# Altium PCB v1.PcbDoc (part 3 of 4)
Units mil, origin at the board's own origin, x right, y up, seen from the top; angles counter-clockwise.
Board outline 4875 x 2022 mil, 4 copper layers (Top Layer, Signal Layer 1, Signal Layer 2, Bottom Layer), stack 64.834 mil thick; 432 components, 288 nets, 1177 pads, 637 vias.
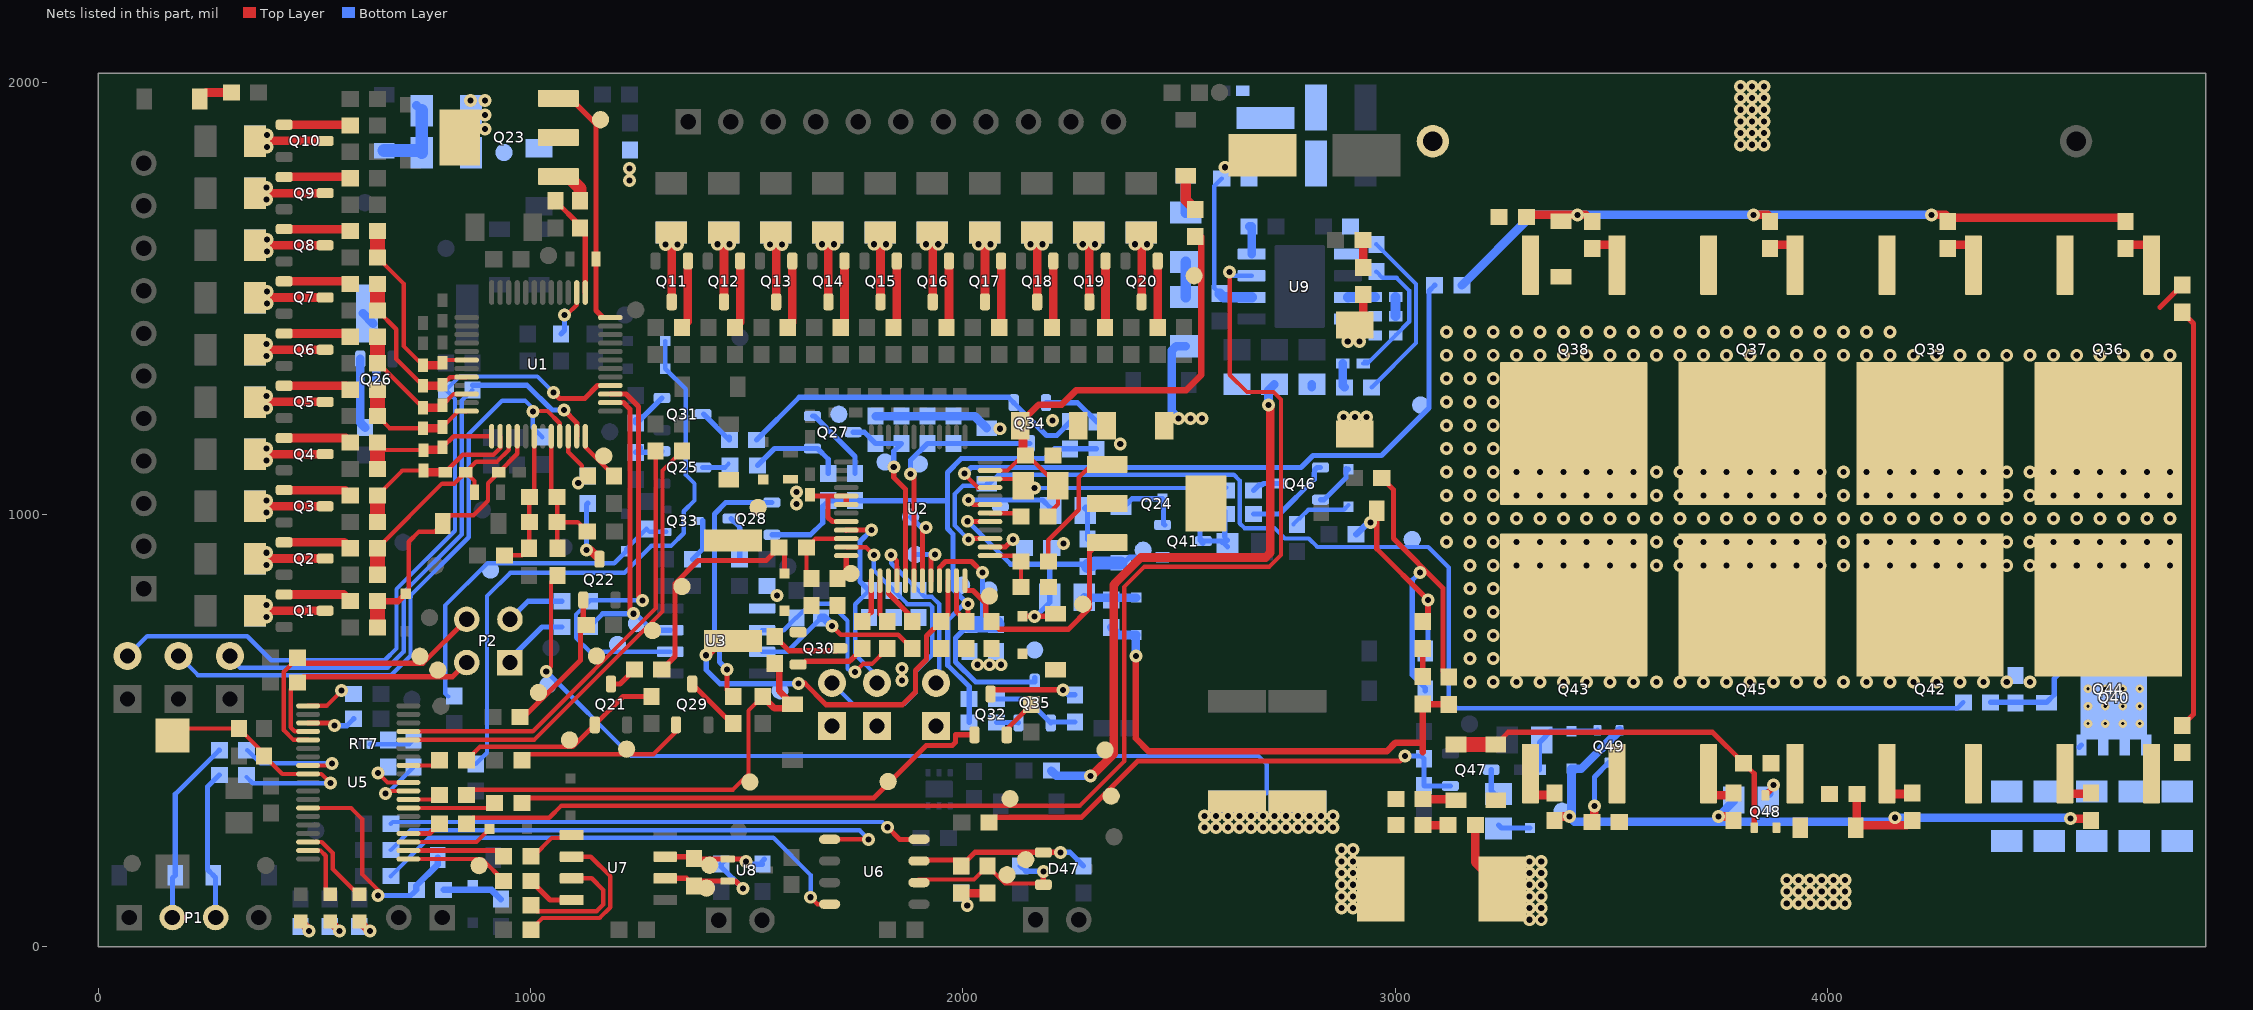
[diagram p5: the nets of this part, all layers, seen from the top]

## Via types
v1: diameter 30, hole 14, Top Layer to Bottom Layer, 615 vias
v2: diameter 19.68, hole 7.87, Top Layer to Bottom Layer, 18 vias
v3: diameter 19.68, hole 7.87, Top Layer to Bottom Layer, tented both sides, 4 vias

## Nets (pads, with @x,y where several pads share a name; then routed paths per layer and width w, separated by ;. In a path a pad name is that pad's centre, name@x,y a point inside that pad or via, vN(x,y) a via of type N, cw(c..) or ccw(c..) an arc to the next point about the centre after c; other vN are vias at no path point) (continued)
LED2: D43.2 U5.18 | length 138.8
  Top Layer w10: U5.18@484.86,223.17 513.83,223.17 526,211 526,132.5 D43.2@536,122.5
LED3: D44.2 U5.17 | length 190.9
  Top Layer w10: U5.17@484.86,242.85 516.77,242.85 542,217.63 542,180.23 599.73,122.5 D44.2@604,122.5
NetC27_1: C27.1 R92.2 U1.22 | length 137.7
  Top Layer w10: U1.22@1086.9,1181.66 1086.9,1145.1 1118.5,1113.5 1118.5,1102.87 C27.1@1132,1089.37 C27.1@1122.63,1080
  Bottom Layer w10: R92.2@1122.5,1080 R92.2@1132,1089.5
  other v1: 1110,1073
NetC28_1: C28.1 R93.2 U2.22 | length 176.9
  Top Layer w10: C28.1@1649.54,852.5 1638.01,864.03 R93.2@1638.01,924 1658.75,944.73 U2.22@1730.04,944.73
NetC30_1: C30.1 pad.1@1169,1136 U1.24 | length 119.9
  Top Layer w10: U1.24@1126.27,1181.66 1126.27,1156.83 1193,1090.1 C30.1@1193,1089.37
NetC31_1: C31.1 pad.1@1741,864.03 U2.24 | length 61.2
  Top Layer w12: C31.1@1709.92,852.5 1730.04,872.61 U2.24@1730.04,905.36
NetC40_1: C40.1 pad.1@1161.55,1914 Q23.3 U1.36 | length 583.9
  Top Layer w12: Q23.3@1064.17,1965.55 1089.45,1965.55 1151,1904 C40.1@1151,1592 1151,1472.53 1167.26,1456.27 U1.36@1184.34,1456.27
NetC41_1: C41.1 pad.1@2061,812 pad.1@2277.23,793 Q24.3 U2.36 | length 543.6
  Top Layer w12: U2.36@2004.65,847.29 2004.65,828.35 2008,825 2023,825 2053,795 2053,765.94 C41.1@2065.8,753.15 2083.94,735 2244,735 2293,784 2293,914 Q24.3@2314.45,935.45
NetC44_1: C44.1 pad.1@938,1838 Q23.2 Q23.4 R107.1 R111.1
  other v1: 894,1892 894,1925 861,1958 894,1958
NetC45_1: C45.1 Q24.2 Q24.4 R108.1 | length 199.6
  Bottom Layer w20: v1(2499,1223) 2483.33,1238.67 2483.33,1380 2493.24,1389.91 R108.1@2515.33,1389.91
  other v1: 2526,1223 2553,1223
NetC50_2: C50.2 D16.2 pad.1@907,872 Q33.1 R127.2 | length 804.4
  Bottom Layer w10: R127.2@809,579.5 802,586.5 802,790 900,888 1193.49,888 D16.2@1221.19,915.69 1221.19,920.69 C50.2@1268,967.5 1275.09,960.41 Q33.1@1313.6,960.41
NetC57_1: C57.1 C58.2 | length 977.5
  Top Layer w12: C58.2@4821,512.5 4847,538.5 4847,1442.5 C57.1@4821,1468.5
NetC57_2: C57.2 D17.2 F1.1 Q36.3 Q37.3 Q38.3 Q39.3 R140.2 | length 72.8
  Top Layer w12: 4769.5,1480 C57.2@4821,1531.5
  other v1: 3799,1856 3826,1856 3853,1856 3799,1883 3826,1883 3853,1883 3799,1910 3826,1910 3853,1910 3799,1937 3826,1937 3853,1937 3799,1964 3826,1964 3853,1964 3799,1991 3826,1991 3853,1991
NetC59_1: C59.1 pad.1@2343,349 Q47.1 R162.2 R165.2 | length 1196.3
  Top Layer w12: R162.2@2060.28,288 2072.28,300 2274.03,300 2404.47,430.44 3011.44,430.44 v1(3023,442)
  Bottom Layer w12: v1(3023,442) 3060.5,442 C59.1@3067,435.5 R165.2@3067,373.5 3067.9,372.6 Q47.1@3127.76,372.6
NetC60_1: C60.1 C61.2 | length 58
  Top Layer w20: C60.1@3064.5,282 C61.2@3122.5,282
NetC70_2: C70.2 R205.1 R206.2 | length 61
  Top Layer w20: R206.2@1996,124.5 R205.1@2057,124.5
  other v1: 2010,96
NetC71_1: C71.1 D48.1 L5.1
NetC72_1: C72.1 L5.2 R209.1
NetC73_1: C73.1 C74.1 R209.2 U9.2 | length 356.4
  Bottom Layer w10: C73.1@2594.33,1511.5 2581.33,1524.5 2581.33,1760.5 R209.2@2598.84,1778
  Bottom Layer w25: C73.1@2594.33,1511.5 2602.83,1503 U9.2@2668.11,1503
  other v1: 2606.33,1804
NetC75_1: C75.1 R212.1 | length 64
  Top Layer w20: C75.1@2925.11,1636 2926.33,1634.78 R212.1@2926.33,1572.5
NetC76_1: C76.1 R211.2 | length 44.5
  Bottom Layer w23: C76.1@3000.95,1459.5 R211.2@3000.95,1504
NetC76_2: C76.2 L6.1 pad.1@2917.33,1421 R212.2 R213.1 U9.8 | length 50.8
  Top Layer w20: L6.1@2926.33,1462.98 R212.2@2926.33,1509.5
  Bottom Layer w10: U9.8@2890.55,1453 U9.8@2893.55,1456
  other v1: 2890.33,1401 2917.33,1401
NetC77_1: C77.1 C78.2 R213.2 | length 320.7
  Bottom Layer w10: C78.2@2925.97,1350 2935.95,1350 R213.2@3000.95,1415 3032.33,1446.38 3032.33,1519 3003.33,1548 2971.04,1548 C77.1@2956.53,1562.5 ; C78.2@2928.95,1354 C78.2@2936.95,1354
NetC77_2: C77.2 R214.2 R215.1 U9.5 | length 411.3
  Bottom Layer w10: R215.1@2945.83,1294.7 3048.33,1397.2 3048.33,1533.7 C77.2@2956.53,1625.5
NetC78_1: C78.1 C79.1 C80.1 C81.1 L6.2 pad.1@2328.86,455.7 R215.2 R216.1 | length 1415
  Top Layer w20: v1(2295,396) 2298,396 2349.25,447.25 2349.25,837.75 2352,840.5 2352,841.45 2411.55,901 2700,901 2711,912 2711,1250 v1(2707,1254)
  Bottom Layer w20: R216.1@2204.5,408 2216.5,396 v1(2295,396) ; v1(2707,1254) 2707,1288.17 C80.1@2720.33,1301.5 ; C81.1@2807.33,1294.7 C81.1@2807.33,1301.5 ; C78.1@2878.73,1350 2878.73,1298.81 R215.2@2882.84,1294.7
  other v1: 2880,1226 2907,1226 2934,1226
NetD8_1: D8.1 R88.1 | length 79.2
  Top Layer w20: D8.1@234.47,1962 249.47,1977 R88.1@307.5,1977
NetD9_1: D9.1 R90.1 | length 87.1
  Top Layer w25: D9.1@2515.33,1784.53 2515.33,1728.5 R90.1@2537.33,1706.5
NetD10_1: D10.1 pad.1@1349.81,833.77 R89.2 R93.1 | length 551.7
  Top Layer w12: R89.2@1303.2,642 1333.5,672.3 1333.5,840.43 1386.91,893.83 1544.86,893.83 R93.1@1575.02,924 1587.06,911.96 D10.1@1587.06,864.36
NetD11_1: D11.1 R107.2 R111.2 | length 202.8
  Bottom Layer w20: R111.2@735.91,1947 R111.2@747.91,1935 ; R107.2@743.38,1842.53 R107.2@747.91,1838
  Bottom Layer w30: D11.1@661,1842.53 R107.2@743.38,1842.53 ; R107.2@747.91,1838 R111.2@747.91,1935
NetD12_1: D12.1 R109.2 | length 93.9
  Bottom Layer w23: R109.2@2515.33,1699.09 R109.2@2521.33,1705.09
  Bottom Layer w25: R109.2@2515.33,1699.09 D12.1@2515.33,1784.53
NetD13_1: D13.1 D14.1 R120.1 | length 1397.6
  Bottom Layer w10: R120.1@873,423.5 899,449.5 899,812 953,866 1217,866 1279,928 1324.71,928 1354,957.29 1354,1008.03 1379,1033.03 1379,1072.04 1359.06,1091.99 1359.06,1290.25 D13.1@1311.31,1338 D14.1@1311.31,1402
NetD17_1: D17.1 R139.2 R140.1 R141.1 R142.1 R143.1 R144.1 | length 1797.5
  Top Layer w20: R140.1@3303.5,1688.78 3308.71,1694 v1(3422,1694) 3440.5,1694 R143.1@3456,1678.5 ; v1(3829,1694) 3861.5,1694 R142.1@3868,1687.5 ; v1(4241,1694) 4273.5,1694 4280,1687.5 R141.1@4678.99,1687.5
  Bottom Layer w20: R139.2@3154.5,1531 3317.5,1694 v1(3422,1694) v1(3829,1694) v1(4241,1694)
NetD19_1: D19.1 Q36.2 Q37.2 Q38.2 Q39.2 Q40.1 Q40.2 Q40.3 Q42.2 Q43.2 Q44.2 Q45.2 R146.1
  other v1: 3173,613 3227,613 3281,613 3335,613 3389,613 3443,613 3497,613 3551,613 3605,613 3659,613 3713,613 3767,613 3821,613 3875,613 3929,613 3983,613 4037,613 4091,613 4145,613 4199,613 4253,613 4307,613 4361,613 4415,613 4469,613 3173,667 3227,667 3173,721 3227,721 3173,775 3227,775 3173,829 3227,829 3173,883 3227,883 3281,883 3335,883 3389,883 3443,883 3497,883 3551,883 3605,883 3659,883 3713,883 3767,883 3821,883 3875,883 3929,883 3983,883 4037,883 4091,883 4145,883 4199,883 4253,883 4307,883 4361,883 4415,883 4469,883 4523,883 4577,883 4631,883 4685,883 4739,883 4793,883 3119,937 3173,937 3227,937 3281,937 3335,937 3389,937 3443,937 3497,937 3551,937 3605,937 3659,937 3713,937 3767,937 3821,937 3875,937 3929,937 3983,937 4037,937 4091,937 4145,937 4199,937 4253,937 4307,937 4361,937 4415,937 4469,937 4523,937 4577,937 4631,937 4685,937 4739,937 4793,937 3119,991 3173,991 3227,991 3281,991 3335,991 3389,991 3443,991 3497,991 3551,991 3605,991 3659,991 3713,991 3767,991 3821,991 3875,991 3929,991 3983,991 4037,991 4091,991 4145,991 4199,991 4253,991 4307,991 4361,991 4415,991 4469,991 4523,991 4577,991 4631,991 4685,991 4739,991 4793,991 3119,1045 3173,1045 3227,1045 3281,1045 3335,1045 3389,1045 3443,1045 3497,1045 3551,1045 3605,1045 3659,1045 3713,1045 3767,1045 3821,1045 3875,1045 3929,1045 3983,1045 4037,1045 4091,1045 4145,1045 4199,1045 4253,1045 4307,1045 4361,1045 4415,1045 4469,1045 4523,1045 4577,1045 4631,1045 4685,1045 4739,1045 4793,1045 3119,1099 3173,1099 3227,1099 3281,1099 3335,1099 3389,1099 3443,1099 3497,1099 3551,1099 3605,1099 3659,1099 3713,1099 3767,1099 3821,1099 3875,1099 3929,1099 3983,1099 4037,1099 4091,1099 4145,1099 4199,1099 4253,1099 4307,1099 4361,1099 4415,1099 4469,1099 4523,1099 4577,1099 4631,1099 4685,1099 4739,1099 4793,1099 3119,1153 3173,1153 3227,1153 3119,1207 3173,1207 3227,1207 3119,1261 3173,1261 3227,1261 3119,1315 3173,1315 3227,1315 3119,1369 3173,1369 3227,1369 3281,1369 3335,1369 3389,1369 3443,1369 3497,1369 3551,1369 3605,1369 3659,1369 3713,1369 3767,1369 3821,1369 3875,1369 3929,1369 3983,1369 4037,1369 4091,1369 4145,1369 4199,1369 4253,1369 4307,1369 4361,1369 4415,1369 4469,1369 4523,1369 4577,1369 4631,1369 4685,1369 4739,1369 4793,1369 3119,1423 3173,1423 3227,1423 3281,1423 3335,1423 3389,1423 3443,1423 3497,1423 3551,1423 3605,1423 3659,1423 3713,1423 3767,1423 3821,1423 3875,1423 3929,1423 3983,1423 4037,1423 4091,1423 4145,1423
NetD19_2: D19.2 Q40.4 R145.2 R146.2 | length 440.1
  Bottom Layer w12: R145.2@4377.5,566 4506.53,566 D19.2@4507,565.53 4525,583.53 4525,621 4549,645 4709,645 4738,674 Q40.4@4738,686.5
NetD21_1: D21.1 D22.1 Q41.2 R147.1 R148.2 | length 326.1
  Bottom Layer w12: R148.2@2288,943.5 2288,1008.74 2281.77,1014.97 2284.27,1017.47 2372,1017.47 2384.02,1029.48 2384.02,1029.97 2391.05,1037 D22.1@2461.69,1037 2464.22,1034.47 2464.22,978.93 Q41.2@2466.76,976.4
NetD22_2: D22.2 Q41.3 R156.1 R157.2 | length 247.3
  Bottom Layer w12: Q41.3@2548.31,940.94 Q41.3@2555.74,933.5 ; D22.2@2548.31,1037 2548.31,944.81 2554.12,939 2561.24,939 R157.2@2605.61,939 ; R157.2@2599.13,935.5 R157.2@2601.63,938 ; R157.2@2602.61,935.39 R157.2@2612,926 ; R157.2@2602.61,939 2610,939 R157.2@2612,941 ; R157.2@2605.61,950.39 R156.1@2605.61,1008.27
NetD24_1: D24.1 R155.1 R163.2 | length 120.4
  Bottom Layer w20: R155.1@2281,809.31 2282,808.31 2343,808.31 D24.1@2401,808.31
NetD25_1: D25.1 R164.2 | length 146.3
  Bottom Layer w10: R164.2@2765,977.5 2765,978.48 2778.7,992.18 2779.69,992.18 2799.29,1011.79 2881.09,1011.79 D25.1@2892,1022.69
NetD25_2: D25.2 Q46.2 | length 110
  Bottom Layer w12: Q46.2@2827.24,1034.6 2835.12,1034.6 2886.19,1085.67 D25.2@2886.19,1099.5 ; D25.2@2886.19,1107.32 D25.2@2886.19,1099.5 ; D25.2@2892,1105.31 D25.2@2886.19,1099.5
NetD28_1: D28.1 R168.2 | length 76
  Bottom Layer w12: R168.2@3239,282.5 3246.29,275.21 D28.1@3312,275.21
NetD29_1: D29.1 D30.2 Q49.1 R166.2 | length 209.6
  Bottom Layer w12: D29.1@3333.65,410 3333.65,473.15 R166.2@3339.5,479 3359.81,499.31 D30.2@3408,499.31 3466.31,499.31 Q49.1@3468.41,501.4
NetD30_1: D30.1 D31.1 pad.1@3386,314 Q49.2 R158.2 R159.2 R160.2 R161.2 R167.1 R171.1 | length 1812.1
  Top Layer w20: R159.2@3369,293 3378,302 v1(3403,302) ; v1(3748,302) 3773.6,302 R161.2@3782.6,293 ; D31.1@4066,276 D31.1@4067.97,277.97 ; R167.1@4068,354 D31.1@4067.97,277.97 ; R158.2@4192,291.01 4182.99,282 4072,282 D31.1@4067.97,277.97 ; v1(4563,297) 4595.5,297 4601.5,291 R160.2@4602,291.5
  Bottom Layer w20: v1(3403,302) v1@3408,297 ; Q49.2@3519.59,501.4 3430.88,412.69 D30.1@3408,412.69 v1@3408,297 ; v1(3748,302) 3783,337 R171.1@3783,340 ; v1(4563,297) 4561,299 v1(4156,299) 4147,290 3415,290 v1@3408,297
NetD32_1: D32.1 D35.1 R169.2 R172.1 | length 483.5
  Top Layer w12: D32.1@2957.47,1009 2957.47,921.53 v1(3076,803)
  Top Layer w15: R172.1@3064,753 3076,765 v1(3076,803)
  Bottom Layer w12: D35.1@3069.47,685 3076,691.53 v1(3076,803)
  Bottom Layer w15: R169.2@2909.5,955 2910.48,955 2934.61,979.13 2940.13,979.13 v1(2943,982) v1@2935,982
NetD33_1: D33.1 R170.2 R177.1 | length 817.4
  Top Layer w12: R170.2@2969,1085 2996,1058 2996,945 3111,830 3111,637.5 R177.1@3124,624.5
  Bottom Layer w12: v1(3057,866) 3039.46,848.46 3039.46,629.02 3069.47,599 D33.1@3069.47,593
NetD34_1: D34.1 D36.1 Q48.1 R174.2 | length 866.2
  Top Layer w12: D34.1@3233,468.47 3261.53,497 3734.5,497 R174.2@3806.5,425 3830.82,400.69 Q48.1@3830.82,276
  Top Layer w35: D36.1@3141,468.47 D34.1@3233,468.47
NetD36_2: D36.2 R173.2 | length 76
  Top Layer w20: R173.2@3064.5,342 3135.47,342 D36.2@3138.47,339
  Top Layer w30: D36.2@3138.47,339 D36.2@3139,339.53
NetD38_2: D38.2 R178.1 R179.2 | length 141.4
  Bottom Layer w15: R179.2@798.5,132 909.5,132 R178.1@931,110.5
NetD39_1: D39.1 R179.1 U5.13 | length 517.3
  Top Layer w10: U5.13@484.86,321.59 584.52,321.59 610,296.11 610,168.56 647,131.56 v1(647,119)
  Bottom Layer w12: v1(647,119) 722.5,119 728.5,125 R179.1@735.5,132
  Bottom Layer w15: R179.1@735.5,132 735.5,141.5 784.53,190.53 D39.1@784.53,207
NetD40_1: D40.1 P1.3 R187.2 | length 349.3
  Bottom Layer w12: P1.3@271,68 271,160.53 D40.1@265.53,166 252,179.53 252,370.5 R187.2@279.5,398
NetD41_1: D41.1 P1.2 R188.2 | length 432.2
  Bottom Layer w12: P1.2@171,68 171,159.53 D41.1@177.47,166 177.47,353.26 R188.2@279.5,455.3
NetD42_1: D42.1 R189.2 | length 29.8
  Top Layer w20: D42.1@468,58.82 487.25,39.57 v1(487.25,37)
NetD43_1: D43.1 R190.2 | length 30.8
  Top Layer w20: D43.1@536,58.82 557.63,37.2 v1(557.63,37)
NetD44_1: D44.1 R191.2 | length 33
  Top Layer w20: D44.1@604,58.82 625.82,37 v1(628,37)
NetD46_2: D46.2 U5.22 | length 200
  Top Layer w10: U5.22@717.14,242.85 874.55,242.85 D46.2@904.69,273
NetD47_1: D47.1 L2.2 pad.1@2145.3,202 R206.1 U6.7 | length 422
  Top Layer w12: U6.7@1890.02,199 1892.02,201 1982.5,201 R206.1@1996,187.5 2027.68,219.18 2185.62,219.18 D47.1@2186,218.8 2186.2,219 v1(2226,219)
  Bottom Layer w12: v1(2226,219) 2247.67,219 L2.2@2279.17,187.5
NetD47_2: D47.2 L1.2 pad.1@2102,167 R205.2 U6.6 | length 415.1
  Top Layer w10: U6.6@1890.02,149 1897.02,156 2025.5,156 R205.2@2057,187.5 2097.46,147.04 D47.2@2186,147.04
  Top Layer w12: D47.2@2186,147.04 v1(2186,175)
  Bottom Layer w12: L1.2@2132.76,187.5 2145.26,175 v1(2186,175)
NetL3_2: L3.2 pad.1@1406.7,136.1 R208.1 U7.6 U8.2 | length 296.6
  Top Layer w12: U7.6@1296.06,158.84 1360.66,158.84 R208.1@1378,141.5 ; R208.1@1378,148.5 1381.91,152.41 U8.2@1455.71,152.41 1473.59,152.41 v1(1491,135)
  Bottom Layer w12: L3.2@1441,191.5 1441,185 v1(1491,135) ; L3.2@1441,203.5 L3.2@1447,197.5
NetL4_2: L4.2 pad.1@1414,189.11 R208.2 U7.7 U8.1 | length 257.1
  Top Layer w12: U7.7@1296.06,208.84 1375.35,208.84 1378,211.5 1385.91,203.59 U8.1@1455.71,203.59 1492.41,203.59 v1(1498,198)
  Bottom Layer w12: v1(1498,198) 1504.5,191.5 L4.2@1536,191.5 ; L4.2@1535.5,198 L4.2@1541,203.5
NetP2_1: P2.1 R195.2 | length 159.2
  Bottom Layer w12: P2.1@952,658 952,666 1026,740 R195.2@1072.5,740
NetP2_3: P2.3 R192.2 | length 150.6
  Bottom Layer w10: P2.3@930,758 P2.3@939,767
  Bottom Layer w12: P2.3@952,758 994,800 R192.2@1072.5,800
NetQ1_1: Q1.1 R22.1 | length 159.1
  Top Layer w20: Q1.1@429.76,815.4 567.26,815.4 R22.1@582.5,800.16
NetQ1_3: Q1.3 R1.2 R2.2 | length 162.3
  Top Layer w20: R2.2@362.09,777.71 362.37,778 Q1.3@524.24,778
  other v1: 389.16,763.38 389.16,791.38
NetQ2_1: Q2.1 R24.1 | length 158.4
  Top Layer w20: Q2.1@429.76,936.18 568.8,936.18 R24.1@582.5,922.47
NetQ2_3: Q2.3 R3.2 R4.2 | length 162.3
  Top Layer w20: R4.2@362.09,898.47 362.39,898.78 Q2.3@524.24,898.78
  other v1: 389.16,884.14 389.16,912.14
NetQ3_1: Q3.1 R26.1 | length 157.8
  Top Layer w20: Q3.1@429.76,1056.96 570.34,1056.96 R26.1@582.5,1044.79
NetQ3_3: Q3.3 R5.2 R6.2 | length 162.3
  Top Layer w20: R6.2@362.09,1019.23 362.41,1019.56 Q3.3@524.24,1019.56
  other v1: 389.16,1004.9 389.16,1032.9
NetQ4_1: Q4.1 R28.1 | length 157.2
  Top Layer w20: Q4.1@429.76,1177.73 571.87,1177.73 R28.1@582.5,1167.1
NetQ4_3: Q4.3 R7.2 R8.2 | length 162.3
  Top Layer w20: R8.2@362.09,1139.99 362.43,1140.33 Q4.3@524.24,1140.33
  other v1: 389.16,1125.66 389.16,1153.66
NetQ5_1: Q5.1 R30.1 | length 156.5
  Top Layer w20: Q5.1@429.76,1298.51 573.41,1298.51 R30.1@582.5,1289.42
NetQ5_3: Q5.3 R9.2 R10.2 | length 162.3
  Top Layer w20: R10.2@362.09,1260.75 362.45,1261.11 Q5.3@524.24,1261.11
  other v1: 389.16,1246.42 389.16,1274.42
NetQ6_1: Q6.1 R32.1 | length 155.9
  Top Layer w20: Q6.1@429.76,1419.29 574.95,1419.29 R32.1@582.5,1411.74
NetQ6_3: Q6.3 R11.2 R12.2 | length 162.3
  Top Layer w20: R12.2@362.09,1381.51 362.47,1381.89 Q6.3@524.24,1381.89
  other v1: 389.16,1367.17 389.16,1395.17
NetQ7_1: Q7.1 R34.1 | length 155.2
  Top Layer w20: Q7.1@429.76,1540.07 576.49,1540.07 R34.1@582.5,1534.05
NetQ7_3: Q7.3 R13.2 R14.2 | length 162.3
  Top Layer w20: R14.2@362.09,1502.26 362.49,1502.67 Q7.3@524.24,1502.67
  other v1: 389.58,1488.35 389.58,1516.35
NetQ8_1: Q8.1 R36.1 | length 154.6
  Top Layer w20: Q8.1@429.76,1660.85 578.03,1660.85 R36.1@582.5,1656.37
NetQ8_3: Q8.3 R15.2 R16.2 | length 162.3
  Top Layer w20: R16.2@362.09,1623.02 362.51,1623.44 Q8.3@524.24,1623.44
  other v1: 389.58,1609.11 389.58,1637.11
NetQ9_1: Q9.1 R38.1 | length 154
  Top Layer w20: Q9.1@429.76,1781.62 579.56,1781.62 R38.1@582.5,1778.68
NetQ9_3: Q9.3 R17.2 R18.2 | length 162.3
  Top Layer w20: R18.2@362.09,1743.78 362.53,1744.22 Q9.3@524.24,1744.22
  other v1: 389.16,1729.45 389.16,1757.45
NetQ10_1: Q10.1 R40.1 | length 153.3
  Top Layer w20: Q10.1@429.76,1902.4 581.1,1902.4 R40.1@582.5,1901
NetQ10_3: Q10.3 R19.2 R20.2 | length 162.3
  Top Layer w20: R20.2@362.09,1864.54 362.55,1865 Q10.3@524.24,1865
  other v1: 389.62,1850.67 389.62,1878.67
NetQ11_1: Q11.1 R65.1 | length 159.3
  Top Layer w20: R65.1@1350.39,1433.5 1363.73,1446.84 Q11.1@1363.73,1587.24
NetQ11_3: Q11.3 R42.2 R43.2 | length 160.5
  Top Layer w20: R42.2@1325.49,1652.91 1326.33,1652.07 Q11.3@1326.33,1492.76
  other v1: 1312,1625 1340,1625
NetQ12_1: Q12.1 R67.1 | length 158.7
  Top Layer w20: R67.1@1472.64,1433.5 1484.51,1445.36 Q12.1@1484.51,1587.24
NetQ12_3: Q12.3 R44.2 R45.2 | length 159.3
  Top Layer w20: Q12.3@1447.11,1492.76 R44.2@1447.11,1652.06
  other v1: 1431.92,1625.84 1459.92,1625.84
NetQ13_1: Q13.1 R69.1 | length 158.1
  Top Layer w20: R69.1@1594.9,1433.5 1605.29,1443.89 Q13.1@1605.29,1587.24
NetQ13_3: Q13.3 R46.2 R47.2 | length 160.5
  Top Layer w20: R46.2@1567.01,1652.91 1567.89,1652.04 Q13.3@1567.89,1492.76
  other v1: 1553.56,1624.96 1581.56,1624.96
NetQ14_1: Q14.1 R71.1 | length 157.4
  Top Layer w20: R71.1@1717.15,1433.5 1726.07,1442.41 Q14.1@1726.07,1587.24
NetQ14_3: Q14.3 R48.2 R49.2 | length 160.5
  Top Layer w20: R48.2@1687.77,1652.91 1688.66,1652.02 Q14.3@1688.66,1492.76
  other v1: 1673.44,1625.84 1701.44,1625.84
NetQ15_1: Q15.1 R73.1 | length 156.8
  Top Layer w20: R73.1@1839.4,1433.5 1846.84,1440.94 Q15.1@1846.84,1587.24
NetQ15_3: Q15.3 R50.2 R51.2 | length 160.5
  Top Layer w20: R50.2@1808.53,1652.91 1809.44,1652 Q15.3@1809.44,1492.76
  other v1: 1794.2,1625.84 1822.2,1625.84
NetQ16_1: Q16.1 R75.1 | length 156.2
  Top Layer w20: R75.1@1961.65,1433.5 1967.62,1439.46 Q16.1@1967.62,1587.24
NetQ16_3: Q16.3 R52.2 R53.2 | length 160.5
  Top Layer w20: R52.2@1929.29,1652.91 1930.22,1651.98 Q16.3@1930.22,1492.76
  other v1: 1914.95,1625.84 1942.95,1625.84
NetQ17_1: Q17.1 R77.1 | length 155.6
  Top Layer w20: R77.1@2083.91,1433.5 2088.4,1437.99 Q17.1@2088.4,1587.24
NetQ17_3: Q17.3 R54.2 R55.2 | length 160.6
  Top Layer w20: R54.2@2050.04,1652.91 2051,1651.96 Q17.3@2051,1492.76
  other v1: 2035.71,1625.84 2063.71,1625.84
NetQ18_1: Q18.1 R79.1 | length 155
  Top Layer w20: R79.1@2206.16,1433.5 2209.18,1436.51 Q18.1@2209.18,1587.24
NetQ18_3: Q18.3 R56.2 R57.2 | length 160.6
  Top Layer w20: R56.2@2170.8,1652.91 2171.78,1651.94 Q18.3@2171.78,1492.76
  other v1: 2156.47,1625.84 2184.47,1625.84
NetQ19_1: Q19.1 R81.1 | length 154.4
  Top Layer w20: R81.1@2328.41,1433.5 2329.95,1435.04 Q19.1@2329.95,1587.24
NetQ19_3: Q19.3 R58.2 R59.2 | length 160.6
  Top Layer w20: R58.2@2291.56,1652.91 2292.55,1651.92 Q19.3@2292.55,1492.76
  other v1: 2277.23,1625.84 2305.23,1625.84
NetQ20_1: Q20.1 R83.1 | length 153.8
  Top Layer w20: R83.1@2450.66,1433.5 2450.73,1433.56 Q20.1@2450.73,1587.24
NetQ20_3: Q20.3 R60.2 R61.2 | length 160.6
  Top Layer w20: R60.2@2412.32,1652.91 2413.33,1651.9 Q20.3@2413.33,1492.76
  other v1: 2397.99,1625.84 2425.99,1625.84
NetQ21_1: pad.1@1090,479.09 Q21.1 R85.2 R86.1 | length 489.3
  Top Layer w10: R85.2@851.5,432 882.57,463.07 1097.33,463.07 Q21.1@1148.3,514.05
  Top Layer w12: Q21.1@1148.3,514.05 1213.75,579.5 R86.1@1279.7,579.5
NetQ21_3: Q21.3 R89.1 | length 68.4
  Top Layer w12: Q21.3@1185.7,608.53 1206.74,608.53 R89.1@1240.2,642
NetQ22_1: pad.1@1018,588.55 Q22.1 R87.2 R91.1 | length 341.1
  Top Layer w12: R87.2@975.5,532 984,532 1115.28,663.28 1115.28,732.78 1127.5,745 1121.6,750.91 Q22.1@1121.6,802.76
NetQ22_3: Q22.3 R92.1 | length 148.3
  Top Layer w20: v1(1129,918) 1138.24,918 Q22.3@1159,897.24
  Bottom Layer w12: v1(1129,918) 1129,1023.5 R92.1@1132,1026.5
NetQ23_1: Q23.1 R105.2 | length 89.9
  Top Layer w30: Q23.1@1064.17,1782.45 1086.81,1782.45 1114,1755.26 R105.2@1114,1726.5
NetQ24_1: Q24.1 R106.2 | length 302.2
  Top Layer w10: R106.2@2197.5,892 2197.5,940.86 2268,1011.37 2268,1086 2304.55,1122.55 Q24.1@2331.83,1122.55
NetQ25_2: Q25.2 R114.2 | length 76.8
  Bottom Layer w12: R114.2@1253.62,1155.11 R114.2@1243,1144.5 1301.35,1144.5 Q25.2@1303.76,1146.9
NetQ25_3: Q25.3 R115.2 | length 63
  Bottom Layer w10: R115.2@1449.58,1109.5 R115.2@1457.79,1117.71
  Bottom Layer w12: Q25.3@1398.24,1109.5 R115.2@1449.58,1109.5
NetQ26_1: Q26.1 R113.2 | length 163.5
  Bottom Layer w20: Q26.1@605.6,1360.24 605.6,1212.9 R113.2@617,1201.5
NetQ26_3: Q26.3 R118.1 | length 190.4
  Bottom Layer w20: R118.1@611.86,1466 R118.1@636,1441.86 ; Q26.3@643,1265.76 R118.1@643,1422
NetQ27_1: Q27.1 R115.1 R116.1 | length 223.8
  Bottom Layer w12: R115.1@1524.5,1114 1564.09,1153.6 Q27.1@1651.76,1153.6 1663.39,1153.6 1688.44,1128.55 R116.1@1688.44,1095.5
NetQ27_2: Q27.2 R117.1 | length 176.4
  Bottom Layer w12: Q27.2@1651.76,1228.4 1656.6,1228.4 1750,1135 R117.1@1750,1095.5
NetQ28_1: Q28.1 R122.1 | length 584.6
  Top Layer w12: v1(1454,642) 1454,594.2 R122.1@1468.7,579.5
  Bottom Layer w12: v1(1454,642) 1437,659 1437,692.87 1424.93,704.94 1424.93,1001.93 1451.4,1028.4 Q28.1@1558,1028.4
NetQ28_3: Q28.3 R126.1 | length 102.2
  Bottom Layer w12: Q28.3@1463.51,991 1483.5,971.01 R126.1@1483.5,897.07
NetQ29_1: pad.1@1222,457.69 Q29.1 R119.2 | length 400.2
  Top Layer w10: R119.2@979.5,432 993.41,445.91 1284.28,445.91 1336.3,497.93 Q29.1@1336.3,514.05
NetQ29_3: Q29.3 R122.2 | length 133.1
  Top Layer w12: Q29.3@1373.7,608.53 1465.73,516.5 R122.2@1468.7,516.5
NetQ30_2: Q30.2 R125.1 | length 155.3
  Top Layer w12: Q30.2@1628.3,653.6 1635.7,661 1736.82,661 1738.82,663 1739.84,663 R125.1@1767,690.16 ; R125.1@1776,688.75 R125.1@1776,690.16
NetQ30_3: Q30.3 R124.1 | length 164.9
  Top Layer w12: R124.1@1564.54,718.5 1597.85,685.19 1707.43,685.19 Q30.3@1713.24,691
NetQ31_2: Q31.2 R128.2 | length 91.9
  Bottom Layer w12: R128.2@1243,1219.65 R128.2@1243,1212.5 1245.86,1212.5 Q31.2@1303.76,1270.4
NetQ31_3: Q31.3 R129.2 | length 91.3
  Bottom Layer w12: Q31.3@1399.5,1233 R129.2@1459.5,1173 R129.2@1459.5,1179.5
NetQ32_2: Q32.2 R132.2 | length 93.1
  Top Layer w12: Q32.2@2101.4,490.89 2101.4,503.9 R132.2@2158,560.5
NetQ32_3: Q32.3 R133.2 | length 203.8
  Top Layer w12: Q32.3@2064,585.37 2073.63,595 v1(2231.8,595)
  Bottom Layer w12: v1(2231.8,595) 2243.3,583.5 R133.2@2259,583.5
NetQ33_3: Q33.3 R137.1 | length 98.8
  Bottom Layer w12: R137.1@1374.5,897 1398.24,920.75 Q33.3@1398.24,986
NetQ34_1: Q34.1 R129.1 R130.1 | length 817
  Bottom Layer w12: R129.1@1522.5,1173 1621.5,1272 2104.84,1272 Q34.1@2117.6,1259.24 2193.35,1183.5 2216.98,1183.5 2248,1214.51 R130.1@2248,1215.5
NetQ34_2: Q34.2 R131.1 | length 135.7
  Bottom Layer w12: Q34.2@2192.4,1259.24 2265.24,1259.24 2309,1215.48 R131.1@2309,1214.5
NetQ35_1: Q35.1 R133.1 R134.1 | length 205.4
  Bottom Layer w12: R134.1@2077.5,574 2147.76,574 Q35.1@2203.4,518.35 2205.55,520.5 R133.1@2259,520.5
NetQ35_2: Q35.2 R135.1 | length 51.4
  Bottom Layer w12: R135.1@2077.5,519 2127.95,519 Q35.2@2128.6,518.35
NetQ36_1: Q36.1 R141.2 | length 104.7
  Top Layer w20: R141.2@4692,1624.5 4750,1624.5 Q36.1@4750,1577.76
NetQ37_1: Q37.1 R142.2 | length 104.1
  Top Layer w20: R142.2@3868,1624.5 3925.33,1624.5 Q37.1@3925.33,1577.76
NetQ38_1: Q38.1 R143.2 | length 103.7
  Top Layer w20: R143.2@3456,1624.5 3513,1624.5 Q38.1@3513,1577.76
NetQ39_1: Q39.1 R144.2 | length 104.4
  Top Layer w20: R144.2@4280,1624.5 4337.67,1624.5 Q39.1@4337.67,1577.76
NetQ40_5: Q40.5 Q40.6 Q40.7 Q40.8 Q40.9 R150.1 R151.1 R152.1 R153.1 R154.1 | length 7.7
  Bottom Layer w12: Q40.8@4582.59,462.09 Q40.8@4588,467.5
  other v2: 4603,517 4643,517 4683,517 4723,517 4603,557 4643,557 4683,557 4723,557 4603,597 4643,597 4683,597 4723,597
NetQ42_1: Q42.1 R158.1 | length 49
  Top Layer w20: Q42.1@4143,354 R158.1@4192,354
NetQ43_1: Q43.1 R159.1 | length 44
  Top Layer w20: Q43.1@3319.98,351.5 R159.1@3364,351.5
NetQ44_1: Q44.1 R160.1 | length 59.5
  Top Layer w20: Q44.1@4542.5,354.5 R160.1@4602,354.5
NetQ45_1: Q45.1 R161.1 | length 50
  Top Layer w20: Q45.1@3727,351 R161.1@3777,351
NetQ46_1: Q46.1 R156.2 | length 211.4
  Bottom Layer w12: R156.2@2672.48,1002 2732.72,1002 2813,1082.28 2813,1096.56 2813.56,1097.12 2813.56,1103.59 2819.37,1109.4 Q46.1@2827.24,1109.4
NetQ46_3: Q46.3 R149.2 | length 66.9
  Bottom Layer w12: R149.2@2672.5,1056 2685.2,1068.7 2691.77,1068.7 2695.07,1072 Q46.3@2732.76,1072
NetQ47_3: Q47.3 R168.1 | length 71.4
  Bottom Layer w12: Q47.3@3222.24,410 3222.24,362.25 R168.1@3239,345.5
NetQ48_3: Q48.3 R171.2 | length 34.7
  Top Layer w15: Q48.3@3856.41,350.8 3875,369.39 v1(3875,375)
  Bottom Layer w20: R171.2@3863,357 R171.2@3865,355
NetQ49_3: Q49.3 R175.1 | length 153.5
  Top Layer w10: v1@3461,322.44 v1(3461,326)
  Top Layer w20: R175.1@3455.5,289 3461,294.5 v1@3461,322.44
  Bottom Layer w12: v1(3461,326) 3461,393.6 Q49.3@3494,426.6
NetR94_2: R94.2 U1.38 | length 123.9
  Top Layer w10: v1(1078,1462) 1083,1462 1106.58,1485.58 U1.38@1106.58,1514.34
  Bottom Layer w10: v1(1078,1462) v1@1078,1471.99
  Bottom Layer w12: R94.2@1070,1418.5 1078,1426.5 v1(1078,1462)
NetR95_2: R95.2 U2.38 | length 60.7
  Top Layer w12: U2.38@2062.72,925.05 2098.05,925.05 v1(2116,943)
NetR96_2: R96.2 U2.42 | length 72.3
  Top Layer w10: U2.42@2062.72,1003.79 2132.48,1003.79 R96.2@2134.3,1001.97
NetR97_1: R97.1 U2.27 | length 117.1
  Top Layer w12: U2.27@1827.48,847.29 1827.48,817.55 1882.88,762.15 R97.1@1882.88,753.15
NetR97_2: R97.2 R104.1 U3.7 | length 415.5
  Top Layer w10: v1(1697,743) 1717.54,722.46 1850.57,722.46 R97.2@1882.88,690.16
  Bottom Layer w10: U3.7@1535.3,683 1593.5,683 R104.1@1672,761.5 ; R104.1@1675.87,757.64 R104.1@1680,761.77
  Bottom Layer w20: R104.1@1672,761.5 1678.5,761.5 1679.12,760.89 v1(1697,743)
NetR98_1: R98.1 U2.26 | length 101.2
  Top Layer w12: U2.26@1807.8,847.29 1807.8,770.26 R98.1@1824.91,753.15
NetR98_2: R98.2 R99.1 U3.6 | length 466.7
  Top Layer w10: v1(1750,636) 1769,655 1789.75,655 R98.2@1824.91,690.16
  Bottom Layer w10: U3.6@1535.3,733 1585.23,733 R99.1@1614,761.77 ; R99.1@1615,761.5 1647.31,793.81 1694.19,793.81 1733.03,754.97 1733.03,643.97 1741,636 v1(1750,636)
NetR100_1: R100.1 R105.1 U1.37 | length 241.3
  Top Layer w12: R100.1@1057,1726.5 1114,1669.5 R105.1@1114,1663.5 ; R105.1@1113,1663.5 1126.27,1650.24 U1.37@1126.27,1514.34
NetR101_1: R101.1 R106.1 U2.37 | length 136.3
  Top Layer w10: U2.37@2062.72,905.36 2121.14,905.36 R106.1@2134.5,892 R101.1@2134.5,833
NetR108_2: R108.2 R109.1 | length 80.8
  Bottom Layer w25: R108.2@2515.33,1504.09 R109.1@2515.33,1584.91
NetR172_2: R172.2 R176.1 | length 64.5
  Top Layer w12: R176.1@3064,625.5 R172.2@3064,690.01
NetR180_2: R180.2 U5.26 | length 204
  Top Layer w10: U5.26@717.14,321.59 905.21,321.59 R180.2@916.45,332.83
NetR181_1: pad.1@1282,732 R181.1 U5.34 | length 1100.6
  Top Layer w10: U5.34@717.14,479.07 1007.88,479.07 1305.06,776.25 1305.06,1102.29 R181.1@1350,1147.24
NetR182_1: R182.1 U5.3 | length 114.9
  Top Layer w12: U5.3@484.86,518.44 539.56,518.44 v1(546,512)
  Bottom Layer w12: v1(546,512) 574.5,512 R182.1@590.5,528
NetR183_2: R183.2 U5.1 | length 92.3
  Top Layer w10: U5.1@484.86,557.81 527.81,557.81 562,592 v1(562,593)
NetR184_1: R184.1 U5.29 | length 80.2
  Top Layer w10: v1(646.19,402.95) 668.48,380.65 U5.29@717.14,380.65
NetR185_1: pad.1@1152.06,673 R185.1 U5.35 | length 1033.9
  Top Layer w10: U5.35@737.14,498.76 1004.76,498.76 1289.06,783.06 R185.1@1289.06,1147.24
NetR186_1: R186.1 U5.27 | length 77.5
  Top Layer w10: U5.27@717.14,341.28 773.78,341.28 R186.1@788.5,356
NetR193_1: R193.1 U6.4 | length 1154.2
  Top Layer w10: v1(1647.58,115.04) 1663.62,99 U6.4@1699.98,99
  Bottom Layer w10: R193.1@676.5,164 765.5,253 1561,253 1647.58,166.42 v1(1647.58,115.04)
NetR194_1: R194.1 U6.8 | length 1231.8
  Top Layer w12: v1(1826,277) 1854,249 U6.8@1890.02,249
  Bottom Layer w10: R194.1@676.5,285 680.5,289 1814,289 v1(1826,277)
NetR196_2: R196.2 U5.23 | length 80.7
  Top Layer w12: U5.23@717.14,262.54 766.04,262.54 R196.2@788.5,285
NetR197_1: R197.1 U6.1 | length 1215.1
  Top Layer w10: U6.1@1699.98,249 v1(1782,249)
  Bottom Layer w10: R197.1@676.5,224.5 722,270 1761,270 v1(1782,249)
NetR201_1: R201.1 U7.4 | length 127.7
  Top Layer w12: R201.1@1000.5,153 1044.65,108.84 U7.4@1109.94,108.84
NetR202_1: R202.1 U7.1 | length 129.7
  Top Layer w10: R202.1@1000.5,210 1006.44,210 1048.44,252 1103.1,252 U7.1@1109.94,258.84
NetR203_2: R203.2 U7.3 | length 290.4
  Top Layer w10: R203.2@1000.5,96.6 1014.1,83 1152.77,83 1168,98.23 1168,132 1141.16,158.84 U7.3@1109.94,158.84
  Top Layer w12: R203.2@1000.5,96.6 R203.2@1008.55,96.6
NetR204_2: R204.2 U7.2 | length 369.9
  Top Layer w10: R204.2@1000.5,40 1027.5,67 1159.4,67 1184,91.6 1184,164 1139.16,208.84 U7.2@1109.94,208.84
NetR210_2: R210.2 U9.4 | length 69.3
  Bottom Layer w20: R210.2@2662.84,1667 2668.11,1667 U9.4@2668.11,1603
NetR211_1: R211.1 U9.7 | length 64.2
  Bottom Layer w23: U9.7@2890.55,1503 2890.55,1504 R211.1@2953.71,1504
PACK+: C58.1 C61.1 D24.2 D31.2 D34.2 D37.1 Q42.3 Q43.3 Q44.3 Q45.3 Q48.2 R150.2 R151.2 R152.2 R153.2 R154.2 R163.1 R167.2 R174.1 R175.2 R176.2 R177.2 | length 1329.7
  Top Layer w15: v1(2400,673) 2400,482.7 2430.2,452.5 2980.5,452.5 3001,473 3059,473 ; 3064,450.25 R176.2@3064,562.5 3065,561.5 R177.2@3124,561.5
  Top Layer w20: C61.1@3185.5,282 3185.5,196 D37.1@3247.49,134
  Bottom Layer w20: R163.1@2343,739.5 2360.81,721.69 D24.2@2401,721.69 ; v1(2400,673) D24.2@2400,720.69
  other v1: 3311,63 3338,63 3311,90 3338,90 3906,101 3933,101 3960,101 3987,101 4014,101 4041,101 3311,117 3338,117 3906,128 3933,128 3960,128 3987,128 4014,128 4041,128 3311,144 3338,144 3906,155 3933,155 3960,155 3987,155 4014,155 4041,155 3311,171 3338,171 3311,198 3338,198
PACK-: C60.2 D37.2 pad.1@1040,606 R102.1 R173.1 R219.2 R220.2 R221.2 R222.2 | length 2055.8
  Top Layer w10: v1(1036,637) 1047,648 1047,844.72 R102.1@1061.78,859.5
  Bottom Layer w10: v1(1036,637) 1037,637 1232,442 2684,442 2703,423 2703,356
  other v1: 2876,90 2903,90 2876,117 2903,117 2876,144 2903,144 2876,171 2903,171 2876,198 2903,198 2876,225 2903,225 2558.77,275.91 2585.77,275.91 2612.77,275.91 2639.77,275.91 2666.77,275.91 2693.77,275.91 2720.77,275.91 2747.77,275.91 2774.77,275.91 2801.77,275.91 2828.77,275.91 2855.77,275.91 2558.77,302.91 2585.77,302.91 2612.77,302.91 2639.77,302.91 2666.77,302.91 2693.77,302.91 2720.77,302.91 2747.77,302.91 2774.77,302.91 2801.77,302.91 2828.77,302.91 2855.77,302.91
PTC_DA: R184.2 R207.1 RT7.2 | length 105.2
  Bottom Layer w10: RT7.2@627.8,469 670.35,469 718.75,469 R207.1@728.79,479.05
PTC_EN: R207.2 U5.28 | length 145.7
  Top Layer w10: v1(664,355) 669.96,360.96 U5.28@717.14,360.96
  Bottom Layer w10: v1(664,355) 667.74,355 R207.2@728.79,416.05
PWR_EN: pad.1@2109,343 R196.1 U9.3 | length 3174.4
  Top Layer w10: R196.1@851.5,286 864.5,299 1043,299 1071,327 2270.55,327 2373,429.45 2373,832.75 2420.25,880 2709,880 2736,907 2736,1266.5 2718.5,1284 2657.15,1284 2617,1324.15 v1(2617,1562)
  Bottom Layer w10: v1@2618.33,1562 v1(2617,1562) 2626,1553 U9.3@2668.11,1553
RXD: R202.2 U5.21 | length 226.1
  Top Layer w12: U5.21@717.31,223 U5.21@717.14,223.17 924.34,223.17 R202.2@937.5,210
SBCLK: R188.1 U5.8 | length 265.3
  Top Layer w10: U5.8@484.86,420.02 535.02,420.02 v1(540,425)
  Bottom Layer w10: R188.1@344.5,455.3 374.8,425 v1(540,425)
SBIO: C67.1 R187.1 R198.1 S1.1 U5.9 | length 628.3
  Top Layer w10: S1.1@171,489.48 186.87,505.35 R198.1@325,505.35 383,447.35 C67.1@383,442.36 383.1,442.36 425.12,400.33 U5.9@484.86,400.33 515.67,400.33 v1(537,379)
  Bottom Layer w10: R187.1@342.5,393.3 356.8,379 v1(537,379)
SCL: pad.1@1245,748 R195.1 U1.26 U3.3 | length 754
  Top Layer w12: U1.26@1184.34,1259.42 1214.58,1259.42 1230,1244 1230,779 v1(1238,771)
  Bottom Layer w12: R195.1@1142.5,733 R195.1@1135.5,740 1166.5,771 v1(1238,771) 1243,771 1281,733 U3.3@1322.7,733
SCL_MCU: P2.2 pad.1@785,641 R200.1 U5.4 | length 564.4
  Top Layer w10: R200.1@461,612 445,596 445,508 454.24,498.76 U5.4@484.86,498.76
  Top Layer w12: R200.1@461,612 474,625 819,625 P2.2@852,658
SDA: pad.1@1201,700 R192.1 U1.27 U3.2 | length 982.2
  Top Layer w12: U1.27@1184.34,1279.1 1220.35,1279.1 1249.34,1250.11 1249.34,811.66 v1(1259,802)
  Bottom Layer w10: v1(1259,802) 1137.5,802 R192.1@1135.5,800 1104.81,769.31 1104.81,715.19 1137,683 U3.2@1322.7,683
SDA_MCU: P2.4 pad.1@743.53,672.61 R199.1 U5.5 | length 684.4
  Top Layer w10: R199.1@461,669 429,637 429,501.37 451.3,479.07 U5.5@484.86,479.07
  Top Layer w12: R199.1@461,669 473.71,656.29 750.29,656.29 P2.4@852,758
SRN: C37.2 C38.2 C42.1 R102.2 U1.20 | length 343.2
  Top Layer w10: U1.20@1047.53,1181.66 1047.53,1053.97 C38.2@1060.5,1041 1061.78,1039.71 C37.2@1061.78,983 ; R102.2@1061.78,922.5 C37.2@1061.78,983 ; C42.1@1130.83,961.07 1108.9,983 C37.2@1061.78,983
SRP: C37.1 C38.1 C43.2 R103.2 U1.18 | length 327.7
  Top Layer w10: C43.2@939.5,906 979.79,906 R103.2@996.28,922.5 996.28,1039.78 C38.1@997.5,1041 1008.16,1051.65 U1.18@1008.16,1181.66
TOP_ALERT: D15.1 pad.1@1507,381.55 R123.2 R124.2 R186.2 | length 1045.3
  Top Layer w10: R186.2@851.5,355 R186.2@851.5,364 ; 871.5,364 1468,364 1504,400 1504,546.8 R123.2@1536.7,579.5
  Top Layer w15: R123.2@1536.7,579.5 1564.2,552 1596.53,552 D15.1@1606,561.47 1575.02,592.45 1575.02,645.03 R124.2@1564.54,655.5
TOP_BAT: C24.2 C26.2 C29.2 pad.1@2535,1553 R90.2 R96.1 U2.47 | length 1154.4
  Top Layer w10: U2.47@2062.72,1102.21 2102.98,1102.21 2137.74,1136.97 C26.2@2145.3,1136.97 2149.8,1136.97 C29.2@2219.8,1066.97 2219.8,1024.47 R96.1@2197.29,1001.97
  Top Layer w15: C24.2@2132.87,1205.97 2132.87,1212.18 2175,1254.31 2228.31,1254.31 2262.5,1288.5 2516.5,1288.5 2551.83,1323.83 2551.83,1643.34 2537.5,1643.34 R90.2@2537.33,1643.5
  Top Layer w20: C24.2@2132.87,1205.97 2139,1199.84 2139,1143.27 C26.2@2145.3,1136.97
TOP_CHG: pad.1@3059,1254 R139.1 U2.45 | length 1499.8
  Top Layer w10: v1(2004,1095) 2004,1093 2034.16,1062.84 U2.45@2062.72,1062.84
  Bottom Layer w12: v1(2004,1095) 2018.54,1109.54 2782.38,1109.54 2810.26,1137.43 2968.43,1137.43 3078,1247 3078,1517.5 R139.1@3091.5,1531
TOP_CP1: C29.1 R149.1 U2.46 | length 524.9
  Top Layer w10: U2.46@2062.72,1082.53 2130.24,1082.53 C29.1@2139.8,1072.97
  Bottom Layer w10: v1(2166,1062) 2608.49,1062 R149.1@2609.49,1063
TOP_DSG: pad.1@2087,1018.54 R147.2 U2.43 | length 270.9
  Top Layer w10: v1(2013,1034) 2023.53,1023.47 U2.43@2062.72,1023.47
  Bottom Layer w12: v1(2013,1034) 2184,1034 2203,1015 R147.2@2203,1010 ; R147.2@2197.75,1004.75 2203,999.5 R147.2@2203,993
TOP_LD: D20.1 D21.2 D23.1 pad.1@2417,918 Q41.1 R148.1 R155.2 U2.41 | length 780.2
  Top Layer w12: v1(2011,985) 2011.9,984.1 U2.41@2062.72,984.1 ; D23.1@2138,767.31 2143.31,762 2146.31,765 v1(2166,765) 2202.53,765 2205.53,762 D20.1@2214,770.47
  Bottom Layer w12: v1(2011,985) 2110.46,885.54 2202,885.54 ; v1(2166,765) 2169,765 2201,797 R155.2@2201,809.31 2201,884.54 2202,885.54 ; R148.1@2288.48,885.54 2202,885.54 ; D21.2@2366,888.53 2372,888.53 2385.07,901.6 Q41.1@2461.76,901.6 Q41.1@2466.76,901.6
  Bottom Layer w30: R148.1@2288,880.5 2288,881.49 2291.7,885.19 2301.07,885.19 2304.41,888.53 D21.2@2366,888.53
TOP_PDSG: D18.1 pad.1@3039.46,942.63 R145.1 U2.39 | length 2985.9
  Top Layer w12: v1(2013,943) 2014.73,944.73 U2.39@2062.72,944.73
  Bottom Layer w10: v1(2013,943) 1981,975 1981,1048 2000,1067 D18.1@2055,1067 ; D18.1@2055,1071.53 2061,1071.53 2082.02,1092.54 2626.9,1092.54 2640.19,1079.26 2640.19,980.35 2651.48,969.05 2721,969.05 2744.87,945.19 2800.14,945.19 2820.03,925.3 3076.63,925.3 3124,877.93 3124,571.5 3143.5,552 4300.5,552 R145.1@4314.5,566
TOP_REG1: C33.1 pad.1@1997,837 Q28.2 R116.2 R117.2 R130.2 R131.2 R134.2 R135.2 U2.35 | length 1618.7
  Top Layer w12: U2.35@1984.96,847.29 1984.96,776.01 C33.1@2007.82,753.15 2012,757.33 v1(2012,793)
  Bottom Layer w12: Q28.2@1558,953.6 1647.6,953.6 1675.57,981.57 1675.57,1019.63 R116.2@1688.44,1032.5 R117.2@1750,1032.5 1963.52,1032.5 1964,1032.98 ; R135.2@2014.5,519 R134.2@2014.5,574 2014.5,602.5 1965,652 1965,756 2002,793 v1(2012,793) 1977,828 1977,954.96 1964,967.96 1964,1032.98 ; R131.2@2309,1152.5 R130.2@2248,1152.5 2212.05,1152.5 2189.55,1130 1996,1130 1964,1098 1964,1032.98
TOP_REG2: C32.1 pad.1@1577,592.88 R112.1 U2.34 | length 928.3
  Top Layer w12: v1(1620,610) 1634,610 1683.5,560.5 1860.5,560.5 1890,590 1890,639.47 1916,665.47 1916,719.3 C32.1@1949.85,753.15 1965.28,768.57 U2.34@1965.28,847.29
  Top Layer w20: v1(1406,675) 1438.86,707.86 R112.1@1468,707.86
  Bottom Layer w12: v1(1406,675) 1406,641 1437.81,609.19 1619.19,609.19 v1(1620,610)
TOP_SHUT: pad.1@1827,382.66 Q32.1 R180.1 | length 1122.8
  Top Layer w12: R180.1@979.44,332.83 991.61,345 1793.69,345 1915.19,466.5 1975.47,466.5 1982.5,473.53 1982.5,490.89 Q32.1@2026.6,490.89
TOP_WAKE: R85.1 U5.31 | length 78
  Top Layer w10: U5.31@717.14,420.02 772.52,420.02 R85.1@788.5,436
TOPAFE_ALERT: R125.2 U2.25 | length 102.9
  Top Layer w12: R125.2@1767,753.15 1788.11,774.26 U2.25@1788.11,847.29
TOPAFE_CFETOFF: C47.1 pad.1@1820,1121.9 Q27.3 R121.2 U2.29 | length 459
  Top Layer w12: v1(1840,1110) 1840,1086 1866.85,1059.15 U2.29@1866.85,847.29
  Bottom Layer w12: Q27.3@1746.24,1191 1772.16,1191 R121.2@1798,1165.16 C47.1@1858.03,1165.16 1840,1147.12 v1(1840,1110)
TOPAFE_DCHG: pad.1@1879,995 U2.31 | length 175.6
  Top Layer w12: U2.31@1906.22,847.29 1906.22,966.22 1910,970 v1(1915,970)
  Bottom Layer w12: pad.1@1879,995 1904,970 v1(1915,970)
TOPAFE_DDSG: pad.1@1890,908 U2.32 | length 113.6
  Top Layer w12: U2.32@1925.91,847.29 1925.91,905.91 1928,908 v1(1935,908)
  Bottom Layer w12: pad.1@1890,908 v1(1935,908)
TOPAFE_DFETOFF: C53.1 pad.1@1899,1117.5 Q34.3 R136.2 U2.30 | length 574.2
  Top Layer w12: v1(1879,1094) 1886.54,1086.46 U2.30@1886.54,847.29
  Bottom Layer w12: v1(1879,1094) 1879,1126.02 C53.1@1918.13,1165.16 1918.53,1164.76 Q34.3@2155,1164.76
TOPAFE_SHUT: C56.1 pad.1@2060,826 Q35.3 R138.2 U2.33 | length 643
  Top Layer w12: U2.33@1945.59,847.29 1945.59,877.59 1960,892 2020,892 v1@2046,866
  Bottom Layer w12: C56.1@2014.87,746.5 1983,714.63 1983,659.46 2029.61,612.84 Q35.3@2166,612.84 Q35.3@2166,623 ; v1(2045,866) 2045,749.66 2048.17,746.5
  Bottom Layer w38: C56.1@2014.87,746.5 2048.17,746.5 R138.2@2076.87,746.5
TS1: C48.1 RT1.2 U1.21 | length 1492.5
  Top Layer w10: 1022,1240 1038.75,1240 1067.21,1211.54 U1.21@1067.21,1181.66
  Bottom Layer w10: RT1.2@185.5,673.5 230,629 677.29,629 722,673.71 722,808.44 723,809.44 723,814.19 856.69,947.88 856.69,1186.69 934,1264 987,1264 1005,1246 v1(1005,1239) 1005,1201.5 C48.1@1027,1179.5
TS2: C51.1 RT3.2 U1.23 | length 1406.8
  Top Layer w12: v1(1077,1242) 1106.58,1212.42 U1.23@1106.58,1181.66
  Bottom Layer w10: RT3.2@304,669.5 327.5,646 669,646 706,683 706,819.81 840.69,954.51 840.69,1264.2 C51.1@865,1288.5
  Bottom Layer w12: C51.1@865,1299.5 991.5,1299.5 1049,1242 v1(1077,1242)
TS3: C54.1 RT5.2 U1.28 | length 1773.4
  Top Layer w12: v1(1052.46,1283) 1066.46,1269 1125,1269 1154.79,1298.79 U1.28@1184.34,1298.79
  Bottom Layer w10: RT5.2@67,669.5 RT5.2@69,671.5 ; RT5.2@67,673.5 112.5,719 344,719 399.7,663.3 662.3,663.3 689.61,690.61 689.61,827.9 824.69,962.99 824.69,1267.81 C54.1@804,1288.5 835.5,1320 1015.46,1320 v1(1052.46,1283) v1@1048.57,1279.1
TS4: C49.1 RT2.2 U2.21 | length 464.9
  Top Layer w12: U2.21@1729.92,964.3 U2.21@1730.04,964.42 1787.88,964.42 v1(1788,964.3)
  Bottom Layer w10: C49.1@1783,824.76 1751,792.76 1751,677 1801,627 RT2.2@1801,611
  Bottom Layer w12: C49.1@1783,824.76 1762,845.76 1762,938.3 v1(1788,964.3)
TS5: C52.1 RT4.2 U2.23 | length 716.9
  Top Layer w10: U2.23@1730.04,925.05 1775.95,925.05 v1(1794,907)
  Bottom Layer w10: RT4.2@1697,611 1746,562 1864.73,562 1890,587.27 1890,637 1929,676 1929,786.76 1922.5,793.27 1871.5,793.27 C52.1@1840,824.76 1794,870.76 v1(1794,907)
TS6: C55.1 RT6.2 U2.28 | length 419.8
  Top Layer w10: v1(1834,907) 1847.17,893.83 1847.17,878.83
  Top Layer w12: U2.28@1847.17,847.29 1847.17,878.83
  Bottom Layer w10: v1(1834,907) 1834,887.76 C55.1@1897,824.76 1911.76,810 1928.39,810 1945,793.39 1945,618 RT6.2@1938,611
TXD: pad.1@880.69,188.19 R201.2 U5.20 | length 241.3
  Top Layer w10: U5.20@717.14,203.48 887.02,203.48 R201.2@937.5,153
UP_GND: C12.2 C22.2 C24.1 C26.1 C28.2 C31.2 C32.2 C33.2 C36.2 C41.2 C45.2 C47.2 C49.2 C52.2 C53.2 C55.2 C56.2 D5.2 D7.2 D10.2 D18.2 D20.2 D23.2 pad.1@1526.16,1017 pad.1@1713,1232.51 pad.1@2166,687 Q30.1 R63.1 R95.1 R101.2 R112.2 R121.1 R136.1 R138.1 RT2.1 RT4.1 RT6.1 U2.17 U2.18 U2.20 U3.5 | length 468.2
  Top Layer w12: C12.2@1646,1041.38 1647.78,1043.16 1688,1043.16 ; U2.20@1730.04,984.1 1697.9,984.1 1688,994 1688,1043.16 ; U2.18@1730.04,1023.47 U2.17@1730.04,1043.16 1688,1043.16
  Bottom Layer w20: R121.1@1798,1228.15 R136.1@1978.3,1228.15 2027.32,1228.15 D18.2@2055,1200.47
  other v1: 1859,617 1859,644 2034,653 2061,653 2088,653 1570,813 2233,934 1615,1025 1615,1053 2364,1164 2086.1,1199 2207,1218 1229,1773 1229,1801
VC0: C1.1 D2.1 D3.1 R21.2 R22.2 U1.16 | length 656.6
  Top Layer w10: D2.1@711,817.31 718,824.31 718,937.41 741.59,961 777.53,961 D3.1@796.53,980 815.53,999 867.83,999 901,1032.17 901,1073.12 C1.1@926.38,1098.5 968.79,1140.91 U1.16@968.79,1181.66
  Top Layer w15: R22.2@645.5,800.15 693.84,800.15 D2.1@711,817.31
  Top Layer w35: R21.2@645.5,739 R22.2@645.5,800.15
VC1: C2.2 C11.1 R23.2 R24.2 U1.15 | length 545.5
  Top Layer w10: R24.2@645.5,922.47 795.02,1072 823.12,1072 C2.2@849.62,1098.5 ; C11.1@870,1052 870,1078.12 C2.2@849.62,1098.5 ; U1.15@949.1,1181.66 949.1,1150.1 922,1123 874.12,1123 C2.2@849.62,1098.5
  Top Layer w35: R23.2@645.5,861.3 R24.2@645.5,922.45
VC2: C2.1 C3.2 R25.2 R26.2 U1.14 | length 420.9
  Top Layer w10: R26.2@645.5,1044.79 703.08,1102.38 C3.2@752,1102.38 ; C2.1@802.38,1098.5 842.88,1139 914,1139 929.42,1154.42 U1.14@929.42,1181.66
  Top Layer w20: C3.2@752,1102.38 755.88,1098.5 C2.1@802.38,1098.5
  Top Layer w35: R25.2@645.5,983.6 R26.2@645.5,1044.75
VC3: C3.1 C4.2 R27.2 R28.2 U1.13 | length 345.9
  Top Layer w10: R28.2@645.5,1167.1 662.98,1149.62 C3.1@752,1149.62 ; C4.2@796,1155.76 821.91,1181.66 U1.13@909.73,1181.66
  Top Layer w20: C3.1@752,1149.62 752.86,1150.48 790.72,1150.48 C4.2@796,1155.76
  Top Layer w35: R27.2@645.5,1105.9 R28.2@645.5,1167.05
VC4: C4.1 C5.2 R29.2 R30.2 U1.12 | length 295.2
  Top Layer w10: R29.2@645.5,1228.26 673.38,1200.38 C5.2@751,1200.38 ; C4.1@796,1203 832.73,1239.73 U1.12@851.66,1239.73
  Top Layer w20: C5.2@751,1200.38 793.38,1200.38 C4.1@796,1203
  Top Layer w35: R29.2@645.5,1228.2 645.5,1228.26 R30.2@645.5,1289.35
VC5: C5.1 C6.2 R31.2 R32.2 U1.10 | length 322.9
  Top Layer w10: R31.2@645.5,1350.58 648.04,1350.58 C5.1@751,1247.62 ; C6.2@796,1253.5 821.6,1279.1 U1.10@851.66,1279.1
  Top Layer w20: C5.1@751,1247.62 790.12,1247.62 C6.2@796,1253.5
  Top Layer w35: R31.2@645.5,1350.58 R32.2@645.5,1411.65
VC6: C6.1 C7.2 R33.2 R34.2 U1.8 | length 388.4
  Top Layer w10: R33.2@645.5,1472.89 689,1429.39 689,1360.38 C7.2@751,1298.38 ; C6.1@796,1300.75 813.72,1318.47 U1.8@851.66,1318.47
  Top Layer w20: C7.2@751,1298.38 793.63,1298.38 C6.1@796,1300.75
  Top Layer w35: R33.2@645.5,1472.8 645.5,1472.89 R34.2@645.5,1533.95
VC7: C7.1 C8.2 R35.2 R36.2 U1.6 | length 460.2
  Top Layer w10: R35.2@645.5,1595.21 706,1534.71 706,1390.62 C7.1@751,1345.62 ; C8.2@796,1351.25 802.59,1357.84 U1.6@851.66,1357.84
  Top Layer w20: C7.1@751,1345.62 790.37,1345.62 C8.2@796,1351.25
  Top Layer w35: R35.2@645.5,1595.1 645.5,1595.21 R36.2@645.5,1656.25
